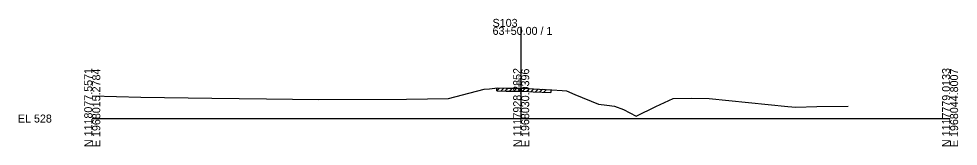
# Model space of a CAD drawing. Extents: x 974 to 1303, y 990 to 14518.
# Drawn here: x 974.3 to 1302.8, y 7990.3 to 8034.9 of the extents above; entities that cross this region are included whole.
import ezdxf

# ---------------------------------------------------------------- set-up
doc = ezdxf.new("R2010")
doc.units = 0
for name, color, linetype in [('Level 10', 7, 'Continuous'), ('Level 60', 7, 'Continuous'), ('Level 61', 7, 'Continuous'), ('Level 63', 7, 'Continuous')]:
    doc.layers.add(name, color=color, linetype=linetype)

msp = doc.modelspace()

# ---------------------------------------------------------------- linework, layer by layer
at = {"layer": 'Level 60'}
for p, q in [((1129.47, 8008.26), (1137.08, 8010.3)), ((1137.08, 8010.3), (1138.91, 8010.44)), ((1138.91, 8010.44), (1141.77, 8010.7)), ((1141.77, 8010.7), (1144.8, 8010.64)), ((1144.8, 8010.64), (1150, 8010.61)), ((1150, 8010.61), (1150.9, 8010.6)), ((1150.9, 8010.6), (1154.21, 8010.4)), ((1154.21, 8010.4), (1160.69, 8010.08)), ((1160.69, 8010.08), (1164.33, 8009.77)), ((1164.33, 8009.77), (1165.85, 8009.66)), ((1165.85, 8009.66), (1168.75, 8008.41)), ((1000, 8007.96), (1016.98, 8007.53)), ((1016.98, 8007.53), (1041.78, 8007.11)), ((1041.78, 8007.11), (1060.99, 8006.85)), ((1060.99, 8006.85), (1079.07, 8006.7)), ((1079.07, 8006.7), (1109.87, 8006.77)), ((1109.87, 8006.77), (1124.6, 8007)), ((1124.6, 8007), (1129.47, 8008.26)), ((1168.75, 8008.41), (1177.04, 8004.99)), ((1197.1, 8004.16), (1203.1, 8006.96)), ((1203.1, 8006.96), (1209.62, 8007.1)), ((1209.62, 8007.1), (1215.7, 8007.06)), ((1215.7, 8007.06), (1243.23, 8004.25)), ((1177.04, 8004.99), (1179.97, 8004.64)), ((1179.97, 8004.64), (1182.64, 8004.32)), ((1182.64, 8004.32), (1185.73, 8003.17)), ((1185.73, 8003.17), (1190.27, 8000.88)), ((1190.27, 8000.88), (1197.1, 8004.16)), ((1243.23, 8004.25), (1246.02, 8004.02)), ((1246.02, 8004.02), (1253.35, 8004.25)), ((1253.35, 8004.25), (1264.41, 8004.29))]:
    msp.add_line(p, q, dxfattribs=at)
at = {"layer": 'Level 61'}
for p, q in [((1141.46, 8009.67), (1142.47, 8010.68)), ((1141.46, 8009.67), (1141.46, 8010.67)), ((1141.46, 8009.67), (1141.77, 8009.7)), ((1141.77, 8009.7), (1144.8, 8009.64)), ((1142.96, 8009.67), (1143.94, 8010.66)), ((1144.46, 8009.65), (1145.45, 8010.63)), ((1144.8, 8009.64), (1150, 8009.61)), ((1145.96, 8009.63), (1146.95, 8010.62)), ((1147.46, 8009.62), (1148.45, 8010.62)), ((1148.96, 8009.61), (1149.95, 8010.61)), ((1150.46, 8009.6), (1151.42, 8010.57)), ((1151.96, 8009.54), (1152.9, 8010.48)), ((1153.46, 8009.45), (1154.4, 8010.39)), ((1154.96, 8009.37), (1155.91, 8010.32)), ((1156.46, 8009.29), (1157.41, 8010.24)), ((1157.96, 8009.21), (1158.91, 8010.17)), ((1160.38, 8010.09), (1160.38, 8009.09)), ((1150, 8009.61), (1150.9, 8009.6)), ((1150.9, 8009.6), (1154.21, 8009.4)), ((1154.21, 8009.4), (1160.38, 8009.09))]:
    msp.add_line(p, q, dxfattribs=at)
at = {"layer": 'Level 63'}
for p, q in [((1150, 8000), (1150, 8032.09)), ((1000, 8000), (1150, 8000)), ((1150, 8000), (1300, 8000))]:
    msp.add_line(p, q, dxfattribs=at)

# ---------------------------------------------------------------- texts
at = {"layer": 'Level 10'}
msp.add_text('538.61', height=0.9, rotation=90, dxfattribs=at).set_placement((1149.95, 8011.11))
at = {"layer": 'Level 63'}
for s, p in [('S103', (1140, 8032.09)), ('63+50.00 / 1', (1140, 8029.29)), ('EL 528', (974, 7998.6))]:
    msp.add_text(s, height=2.8, dxfattribs=at).set_placement(p)
for s, p in [('N 1118077.5571', (1000, 7990)), ('E 1968015.2784', (1002.8, 7990)), ('N 1117928.2852', (1150, 7990)), ('E 1968030.0396', (1152.8, 7990)), ('N 1117779.0133', (1300, 7990)), ('E 1968044.8007', (1302.8, 7990))]:
    msp.add_text(s, height=2.8, rotation=90, dxfattribs=at).set_placement(p)

doc.saveas('drawing.dxf')
